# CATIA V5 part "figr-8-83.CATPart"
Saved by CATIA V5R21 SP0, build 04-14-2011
Part number: Part1
Bounding box of the stored display mesh (mm): x -44.701 to 35.128, y -43.586 to 25.876, z -47.191 to 31.322
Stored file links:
  D:\CATIA V5R21 E-RESOURCES\CATIA-V5R21\catia-v5r21-prt\c08-catia-v5r20-prt\c08-catia-v5r21-figr-8-83.CATPart
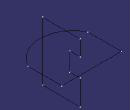
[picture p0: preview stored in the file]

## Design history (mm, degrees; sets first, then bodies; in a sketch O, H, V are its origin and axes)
Body1 (main body)
  Sketch1 on xy-plane, origin (0, 0, 0), H (1, 0, 0), V (0, 1, 0)
    line L1 (-44.7013, 25.8759) -> (35.1284, 25.8759)
    line L2 (35.1284, 25.8759) -> (35.1284, -18.9612)
    line L3 (-44.7013, 25.8759) -> (-44.7013, -18.9612)
    arc A1 centre (-4.7865, 1.0752) radius 44.6615 from (-44.7013, -18.9612) to (35.1284, -18.9612) ccw
    horizontal: L1 H
    vertical: L2 V, L3 V
  Sketch2 on yz-plane, origin (0, 0, 0), H (0, 1, 0), V (0, 0, 1)
    line L1 (-35.2302, 31.3221) -> (-35.2302, -47.1914)
    point P2 (-35.2302, -47.1914)
    point P3 (-35.2302, -47.1914)
    line L2 (-35.2302, -47.1914) -> (15.3919, -47.1914)
    point P4 (15.3919, -47.1914)
    line L3 (15.3919, 31.3221) -> (-35.2302, 31.3221)
    line L4 (15.3919, 31.3221) -> (15.3919, 10.6589)
    line L5 (15.3919, 10.6589) -> (1.7321, 10.6589)
    line L6 (1.7321, 10.6589) -> (1.7321, -13.9018)
    line L7 (1.7321, -13.9018) -> (15.3919, -13.9018)
    point P9 (15.3919, -13.9018)
    line L8 (15.3919, -13.9018) -> (15.3919, -47.1914)
    point P10 (15.3919, -47.1914)
    vertical: L1 V, L4 V, L6 V, L8 V
    horizontal: L2 H, L3 H, L5 H, L7 H
    coincidence: P9 L4, P10 L2, P10 P4, P3 P2
  SolidCombine1: FirstComponentDirection Sketch1, FirstComponentProfile Sketch1, SecondComponentDirection Sketch2, SecondComponentProfile Sketch2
